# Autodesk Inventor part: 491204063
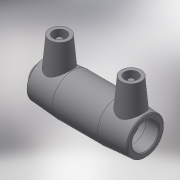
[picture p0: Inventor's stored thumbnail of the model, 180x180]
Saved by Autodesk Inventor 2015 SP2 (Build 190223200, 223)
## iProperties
Created: 2017-06
Part Number: 491204063
Material: Generic
Description: PLASSON END CAP 63
Document SubType Name: Modeling
Designer: KIM
Mass: 38.9236 g
Surface Area: 152.394 cm^2
Volume: 38.9236 cm^3
Density: 1 g/cm^3
Appearance: Default
Author: KIM
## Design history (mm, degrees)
derived "491204.ipt"
feature "Solid1::491204.ipt"
tag "TaggingFeature1"
body "Solid1"
other parameters: "d0" = 117, "d1" = 63, "d2" = 82, "d3" = 57, "d4" = 35.5, "d5" = 73.8, "d6" = 59.85, "d7" = 63, "d8" = 168 deg, "d10" = 22.8, "d11" = 7.6, "d13" = 113.6, "d14" = 17.6296, "d15" = 57, "d16" = 57, "d17" = 59.85, "d18" = 63, "d19" = 3.52592, "d20" = 168 deg, "d22" = 77.08, "d23" = 82, "d24" = 74.7676, "d25" = 135 deg, "d26" = 51.12, "d27" = 135 deg, "d29" = 57, "d30" = 15, "d31" = 45.44, "d34" = 5 deg, "d35" = 15, "d39" = 5 deg, "d41" = 4, "d42" = 14, "d43" = 0, "d45" = 4, "d46" = 14, "d47" = 0, "d48" = 142, "d49" = 1, "d51" = 50.4, "d52" = 2.556, "d53" = 69.3, "d54" = 2.556, "d56" = 6.3, "d57" = 1.89, "d60" = 21.3, "d61" = 1.26, "d63" = 142, "d64" = 1, "d66" = 50.4, "d67" = 12.6, "d68" = 69.3, "d69" = 2.84, "d70" = 0, "d71" = 2.556, "d72" = 3, "d73" = 0, "d74" = 16.53, "d75" = 5.51, "d76" = 3, "d77" = 0, "d_" = 63, "L_" = 142, "L_1" = 57, "D_" = 82, "A_" = 57, "d_2" = 12, "L_0" = 117, "d55" = 6.3
